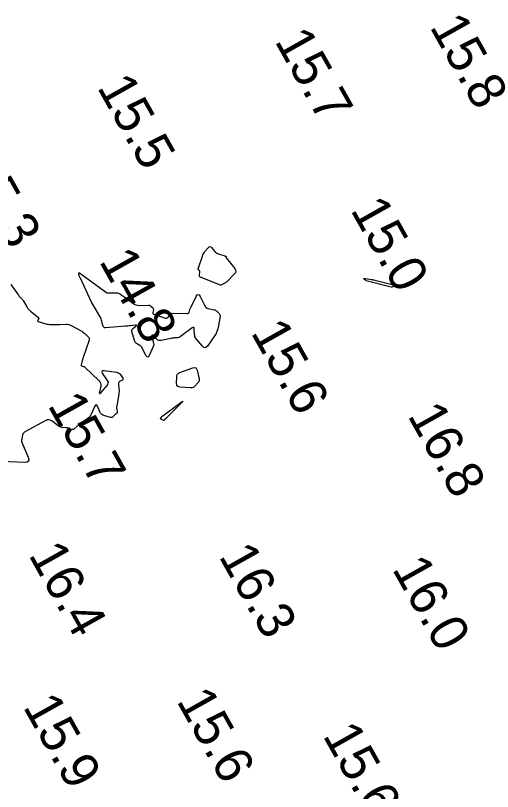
# Model space of a CAD drawing. Extents: x 1023796 to 1112670, y 656573 to 837340.
# Drawn here: x 1108377.1 to 1108440.7, y 683065.1 to 683168.4 of the extents above; entities that cross this region are included whole.
import ezdxf

# ---------------------------------------------------------------- set-up
doc = ezdxf.new("R2010")
doc.units = 0
doc.layers.add('V-CHAN-CONT-15FT', color=7, linetype='Continuous')
doc.layers.add('V-TOPO-SOUN', color=7, linetype='Continuous')

msp = doc.modelspace()

# ---------------------------------------------------------------- linework, layer by layer
at = {"layer": 'V-CHAN-CONT-15FT'}
for points in [[(1108403.02, 683137.62), (1108403.13, 683137.58), (1108403.23, 683137.49), (1108403.65, 683136.99), (1108403.76, 683136.88), (1108403.87, 683136.79), (1108404, 683136.71), (1108404.14, 683136.65), (1108404.98, 683136.38), (1108405, 683136.37), (1108405.02, 683136.37), (1108405.04, 683136.37), (1108405.06, 683136.36), (1108405.13, 683136.35), (1108405.15, 683136.35), (1108405.16, 683136.34), (1108405.16, 683136.33), (1108405.16, 683136.31), (1108405.15, 683136.22), (1108405.15, 683136.2), (1108405.16, 683136.18), (1108405.16, 683136.16), (1108405.18, 683136.14), (1108406.31, 683134.69), (1108406.42, 683134.49), (1108406.45, 683134.3), (1108406.4, 683134.12), (1108406.26, 683133.94), (1108405.33, 683133.01), (1108405.26, 683132.94), (1108405.18, 683132.88), (1108405.09, 683132.82), (1108405.01, 683132.77), (1108404.65, 683132.56), (1108404.56, 683132.53), (1108404.47, 683132.51), (1108404.38, 683132.51), (1108404.28, 683132.54), (1108401.75, 683133.56), (1108401.68, 683133.6), (1108401.63, 683133.66), (1108401.61, 683133.73), (1108401.61, 683133.81), (1108401.68, 683134.27), (1108401.68, 683134.31), (1108401.67, 683134.35), (1108401.65, 683134.38), (1108401.63, 683134.41), (1108401.5, 683134.53), (1108401.48, 683134.56), (1108401.46, 683134.59), (1108401.46, 683134.63), (1108401.46, 683134.67), (1108402, 683136.37), (1108402.06, 683136.53), (1108402.14, 683136.68), (1108402.23, 683136.82), (1108402.33, 683136.96), (1108402.81, 683137.5), (1108402.92, 683137.59)], [(1108385.89, 683133.92), (1108385.94, 683133.89), (1108385.98, 683133.86), (1108389.22, 683131.51), (1108389.25, 683131.48), (1108389.29, 683131.47), (1108389.33, 683131.46), (1108389.38, 683131.46), (1108389.55, 683131.46), (1108389.59, 683131.46), (1108389.64, 683131.47), (1108389.68, 683131.47), (1108389.72, 683131.47), (1108390.55, 683131.48), (1108390.7, 683131.47), (1108390.84, 683131.43), (1108390.97, 683131.38), (1108391.1, 683131.3), (1108392.73, 683130.08), (1108392.93, 683129.95), (1108393.14, 683129.86), (1108393.36, 683129.81), (1108393.59, 683129.8), (1108394.87, 683129.82), (1108394.95, 683129.81), (1108395.02, 683129.79), (1108395.08, 683129.75), (1108395.15, 683129.7), (1108395.38, 683129.47), (1108395.42, 683129.41), (1108395.46, 683129.35), (1108395.47, 683129.27), (1108395.47, 683129.2), (1108395.41, 683128.84), (1108395.41, 683128.76), (1108395.44, 683128.69), (1108395.48, 683128.65), (1108395.55, 683128.61), (1108397.08, 683128.1), (1108397.19, 683128.08), (1108397.28, 683128.09), (1108397.37, 683128.14), (1108397.45, 683128.21), (1108397.73, 683128.58), (1108397.81, 683128.66), (1108397.9, 683128.71), (1108398, 683128.74), (1108398.11, 683128.75), (1108399.99, 683128.71), (1108400.08, 683128.72), (1108400.15, 683128.75), (1108400.2, 683128.81), (1108400.24, 683128.89), (1108400.35, 683129.25), (1108400.38, 683129.34), (1108400.41, 683129.43), (1108400.45, 683129.52), (1108400.49, 683129.6), (1108401.17, 683131), (1108401.3, 683131.19), (1108401.43, 683131.26), (1108401.56, 683131.19), (1108401.69, 683131), (1108402.32, 683129.76), (1108402.4, 683129.62), (1108402.51, 683129.52), (1108402.64, 683129.44), (1108402.79, 683129.39), (1108403.56, 683129.22), (1108403.66, 683129.19), (1108403.76, 683129.15), (1108403.85, 683129.09), (1108403.93, 683129.02), (1108404.24, 683128.72), (1108404.3, 683128.64), (1108404.34, 683128.56), (1108404.36, 683128.46), (1108404.36, 683128.36), (1108404.1, 683126.85), (1108404.04, 683126.56), (1108403.95, 683126.3), (1108403.82, 683126.04), (1108403.67, 683125.79), (1108402.68, 683124.39), (1108402.52, 683124.22), (1108402.36, 683124.16), (1108402.19, 683124.21), (1108402.02, 683124.36), (1108401.2, 683125.32), (1108401.1, 683125.46), (1108401.02, 683125.61), (1108400.98, 683125.77), (1108400.96, 683125.94), (1108400.93, 683126.65), (1108400.91, 683126.79), (1108400.85, 683126.87), (1108400.76, 683126.87), (1108400.63, 683126.79), (1108399.1, 683125.65), (1108399.01, 683125.59), (1108398.91, 683125.54), (1108398.81, 683125.51), (1108398.7, 683125.5), (1108398.26, 683125.46), (1108398.15, 683125.45), (1108398.04, 683125.44), (1108397.93, 683125.42), (1108397.82, 683125.4), (1108396.52, 683125.12), (1108396.36, 683125.11), (1108396.21, 683125.13), (1108396.07, 683125.19), (1108395.95, 683125.29), (1108395.45, 683125.76), (1108395.35, 683125.84), (1108395.29, 683125.85), (1108395.26, 683125.8), (1108395.28, 683125.67), (1108395.47, 683124.74), (1108395.47, 683124.72), (1108395.48, 683124.7), (1108395.49, 683124.68), (1108395.49, 683124.66), (1108395.53, 683124.59), (1108395.53, 683124.57), (1108395.54, 683124.55), (1108395.54, 683124.54), (1108395.53, 683124.52), (1108394.93, 683123.11), (1108394.83, 683122.95), (1108394.73, 683122.89), (1108394.63, 683122.94), (1108394.53, 683123.09), (1108393.99, 683124.11), (1108393.93, 683124.22), (1108393.85, 683124.31), (1108393.76, 683124.4), (1108393.66, 683124.47), (1108393.23, 683124.74), (1108393.13, 683124.82), (1108393.05, 683124.91), (1108392.99, 683125.01), (1108392.95, 683125.13), (1108392.62, 683126.32), (1108392.6, 683126.44), (1108392.62, 683126.54), (1108392.67, 683126.64), (1108392.75, 683126.72), (1108393.14, 683127.04), (1108393.21, 683127.1), (1108393.22, 683127.15), (1108393.18, 683127.17), (1108393.08, 683127.16), (1108392.4, 683127.08), (1108392.25, 683127.06), (1108392.09, 683127.04), (1108391.94, 683127.03), (1108391.78, 683127.02), (1108389.11, 683126.82), (1108388.98, 683126.83), (1108388.87, 683126.88), (1108388.79, 683126.97), (1108388.74, 683127.1), (1108388.62, 683127.69), (1108388.58, 683127.84), (1108388.53, 683127.99), (1108388.47, 683128.12), (1108388.39, 683128.26), (1108387.74, 683129.32), (1108387.61, 683129.55), (1108387.49, 683129.77), (1108387.37, 683130), (1108387.25, 683130.23), (1108385.75, 683133.41), (1108385.73, 683133.45), (1108385.71, 683133.49), (1108385.69, 683133.53), (1108385.67, 683133.57), (1108385.6, 683133.74), (1108385.58, 683133.78), (1108385.57, 683133.82), (1108385.56, 683133.87), (1108385.55, 683133.91), (1108385.54, 683134.09), (1108385.55, 683134.13), (1108385.56, 683134.15), (1108385.58, 683134.15), (1108385.61, 683134.13), (1108385.8, 683133.99), (1108385.85, 683133.95)], [(1108423.78, 683133.37), (1108423.8, 683133.37), (1108424.51, 683133.26), (1108424.63, 683133.24), (1108424.75, 683133.21), (1108424.87, 683133.19), (1108424.99, 683133.16), (1108427.49, 683132.52), (1108427.51, 683132.51), (1108427.52, 683132.5), (1108427.52, 683132.48), (1108427.52, 683132.47), (1108427.47, 683132.38), (1108427.47, 683132.37), (1108427.46, 683132.36), (1108427.45, 683132.35), (1108427.44, 683132.34), (1108427.41, 683132.3), (1108427.4, 683132.29), (1108427.38, 683132.28), (1108427.37, 683132.27), (1108427.36, 683132.27), (1108427.25, 683132.24), (1108427.22, 683132.23), (1108427.2, 683132.23), (1108427.18, 683132.23), (1108427.15, 683132.24), (1108423.84, 683133.08), (1108423.81, 683133.09), (1108423.78, 683133.11), (1108423.75, 683133.12), (1108423.72, 683133.14), (1108423.59, 683133.24), (1108423.58, 683133.25), (1108423.57, 683133.27), (1108423.56, 683133.28), (1108423.55, 683133.29), (1108423.52, 683133.35), (1108423.52, 683133.36), (1108423.52, 683133.37), (1108423.53, 683133.38), (1108423.54, 683133.38), (1108423.64, 683133.39), (1108423.65, 683133.39), (1108423.66, 683133.39), (1108423.68, 683133.39), (1108423.69, 683133.39), (1108423.76, 683133.37)], [(1108401.11, 683121.48), (1108401.24, 683121.36), (1108401.31, 683121.16), (1108401.58, 683120.03), (1108401.59, 683119.88), (1108401.57, 683119.74), (1108401.52, 683119.61), (1108401.42, 683119.49), (1108400.98, 683119.03), (1108400.86, 683118.93), (1108400.73, 683118.86), (1108400.59, 683118.82), (1108400.43, 683118.82), (1108399.01, 683118.91), (1108398.82, 683118.95), (1108398.68, 683119.05), (1108398.6, 683119.19), (1108398.57, 683119.39), (1108398.58, 683120.28), (1108398.61, 683120.48), (1108398.69, 683120.65), (1108398.82, 683120.78), (1108399.01, 683120.87), (1108400.74, 683121.47), (1108400.95, 683121.52)], [(1108396.65, 683115.04), (1108396.69, 683115.07), (1108396.73, 683115.11), (1108399.02, 683116.78), (1108399.32, 683116.99), (1108399.43, 683117.04), (1108399.36, 683116.94), (1108399.11, 683116.68), (1108397.07, 683114.69), (1108397.05, 683114.67), (1108397.03, 683114.65), (1108397.01, 683114.63), (1108397, 683114.6), (1108396.94, 683114.51), (1108396.92, 683114.49), (1108396.9, 683114.48), (1108396.88, 683114.47), (1108396.85, 683114.48), (1108396.49, 683114.64), (1108396.45, 683114.66), (1108396.43, 683114.69), (1108396.43, 683114.73), (1108396.45, 683114.77), (1108396.58, 683114.95), (1108396.61, 683115)]]:
    msp.add_lwpolyline(points, close=True, dxfattribs=at)
msp.add_lwpolyline([(1108376.5, 683132.6), (1108377.5, 683131.14), (1108377.55, 683131.08), (1108377.6, 683131.02), (1108377.65, 683130.96), (1108377.7, 683130.91), (1108377.93, 683130.69), (1108377.98, 683130.64), (1108378.03, 683130.58), (1108378.08, 683130.51), (1108378.12, 683130.45), (1108378.61, 683129.6), (1108378.71, 683129.44), (1108378.83, 683129.3), (1108378.95, 683129.16), (1108379.09, 683129.04), (1108380.15, 683128.18), (1108380.18, 683128.14), (1108380.2, 683128.1), (1108380.2, 683128.05), (1108380.18, 683128), (1108380.06, 683127.8), (1108380.04, 683127.76), (1108380.04, 683127.72), (1108380.06, 683127.69), (1108380.11, 683127.67), (1108381.16, 683127.35), (1108381.31, 683127.31), (1108381.46, 683127.28), (1108381.62, 683127.27), (1108381.77, 683127.26), (1108382.4, 683127.25), (1108382.56, 683127.24), (1108382.71, 683127.25), (1108382.87, 683127.25), (1108383.03, 683127.26), (1108383.83, 683127.3), (1108384.01, 683127.3), (1108384.19, 683127.27), (1108384.36, 683127.22), (1108384.53, 683127.14), (1108385.92, 683126.35), (1108386.04, 683126.27), (1108386.15, 683126.2), (1108386.27, 683126.11), (1108386.37, 683126.02), (1108386.79, 683125.63), (1108386.87, 683125.53), (1108386.92, 683125.42), (1108386.93, 683125.3), (1108386.9, 683125.18), (1108386.11, 683122.85), (1108386.07, 683122.75), (1108386.04, 683122.64), (1108386.01, 683122.53), (1108385.98, 683122.43), (1108385.84, 683121.89), (1108385.83, 683121.84), (1108385.85, 683121.8), (1108385.88, 683121.77), (1108385.92, 683121.75), (1108386.15, 683121.68), (1108386.2, 683121.67), (1108386.25, 683121.64), (1108386.3, 683121.61), (1108386.35, 683121.57), (1108388.24, 683119.75), (1108388.36, 683119.6), (1108388.44, 683119.43), (1108388.46, 683119.25), (1108388.45, 683119.06), (1108388.28, 683118.26), (1108388.25, 683118.1), (1108388.28, 683118.03), (1108388.35, 683118.05), (1108388.46, 683118.16), (1108389.32, 683119.15), (1108389.35, 683119.19), (1108389.37, 683119.22), (1108389.39, 683119.27), (1108389.41, 683119.31), (1108389.47, 683119.49), (1108389.48, 683119.53), (1108389.48, 683119.57), (1108389.47, 683119.62), (1108389.45, 683119.66), (1108388.71, 683120.78), (1108388.62, 683120.95), (1108388.63, 683121.06), (1108388.72, 683121.12), (1108388.92, 683121.12), (1108390.58, 683120.91), (1108390.71, 683120.88), (1108390.83, 683120.83), (1108390.94, 683120.75), (1108391.03, 683120.65), (1108391.4, 683120.12), (1108391.44, 683120.04), (1108391.45, 683119.97), (1108391.41, 683119.91), (1108391.34, 683119.86), (1108390.98, 683119.66), (1108390.9, 683119.61), (1108390.85, 683119.54), (1108390.82, 683119.46), (1108390.82, 683119.36), (1108390.89, 683118.63), (1108390.9, 683118.48), (1108390.9, 683118.32), (1108390.89, 683118.17), (1108390.87, 683118.01), (1108390.59, 683116.37), (1108390.58, 683116.29), (1108390.57, 683116.2), (1108390.58, 683116.12), (1108390.59, 683116.03), (1108390.67, 683115.59), (1108390.68, 683115.56), (1108390.67, 683115.53), (1108390.65, 683115.5), (1108390.63, 683115.47), (1108390.51, 683115.38), (1108390.48, 683115.36), (1108390.45, 683115.33), (1108390.42, 683115.31), (1108390.4, 683115.28), (1108390.06, 683114.95), (1108389.99, 683114.89), (1108389.92, 683114.86), (1108389.84, 683114.86), (1108389.76, 683114.87), (1108388.86, 683115.15), (1108388.69, 683115.23), (1108388.55, 683115.33), (1108388.44, 683115.45), (1108388.35, 683115.61), (1108388.02, 683116.38), (1108387.94, 683116.52), (1108387.86, 683116.57), (1108387.78, 683116.53), (1108387.69, 683116.39), (1108387.19, 683115.31), (1108387.08, 683115.12), (1108386.95, 683114.94), (1108386.79, 683114.79), (1108386.61, 683114.65), (1108385.68, 683114.04), (1108385.58, 683113.97), (1108385.49, 683113.9), (1108385.39, 683113.82), (1108385.31, 683113.73), (1108384.93, 683113.36), (1108384.86, 683113.31), (1108384.78, 683113.27), (1108384.69, 683113.27), (1108384.6, 683113.29), (1108384.22, 683113.42), (1108384.12, 683113.45), (1108384.03, 683113.48), (1108383.93, 683113.5), (1108383.83, 683113.51), (1108383.28, 683113.56), (1108383.16, 683113.58), (1108383.05, 683113.61), (1108382.94, 683113.67), (1108382.84, 683113.73), (1108381.92, 683114.41), (1108381.73, 683114.52), (1108381.54, 683114.56), (1108381.34, 683114.55), (1108381.14, 683114.47), (1108378.36, 683112.96), (1108378.25, 683112.88), (1108378.16, 683112.79), (1108378.09, 683112.68), (1108378.05, 683112.55), (1108377.93, 683112), (1108377.9, 683111.87), (1108377.91, 683111.73), (1108377.93, 683111.6), (1108377.98, 683111.47), (1108378.8, 683109.58), (1108378.89, 683109.27), (1108378.84, 683109.05), (1108378.66, 683108.92), (1108378.34, 683108.89), (1108375.22, 683109.02)], dxfattribs=at)

# ---------------------------------------------------------------- texts
at = {"layer": 'V-TOPO-SOUN'}
for s, p in [('15.8 ', (1108432.23, 683166.91)), ('15.7 ', (1108411.57, 683165.01)), ('15.5 ', (1108387.91, 683158.85)), ('15.3 ', (1108370.03, 683148.38)), ('15.0 ', (1108421.68, 683142.52)), ('14.8 ', (1108388.17, 683135.71)), ('15.6 ', (1108408.4, 683126.2)), ('15.7 ', (1108381.32, 683116.52)), ('16.8 ', (1108429.28, 683115.14)), ('16.4 ', (1108378.76, 683096.6)), ('16.3 ', (1108404.12, 683096.41)), ('16.0 ', (1108427.22, 683094.72)), ('15.6 ', (1108398.49, 683077.15)), ('15.9 ', (1108378.03, 683076.36)), ('15.6 ', (1108417.98, 683072.53))]:
    msp.add_text(s, height=5, rotation=299.3001, dxfattribs=at).set_placement(p)

doc.saveas('drawing.dxf')
